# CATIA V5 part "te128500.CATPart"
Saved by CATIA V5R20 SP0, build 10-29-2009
Part number: 1
Definition: NONE
Nomenclature: 1
Source: Unknown
Description: PART-1-DESC
Bounding box of the stored display mesh (mm): x 0 to 500, y -6 to 6, z -5.85 to 5.85
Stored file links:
  C:\Users\Utente\Desktop\IO LAVORO\3D X SITO CF\CUMSA\3D files TE\te128500.CATPart
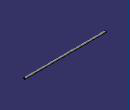
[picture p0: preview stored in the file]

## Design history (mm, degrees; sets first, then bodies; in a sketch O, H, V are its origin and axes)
Body1 "1" (main body)
  Solid1: solid without history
